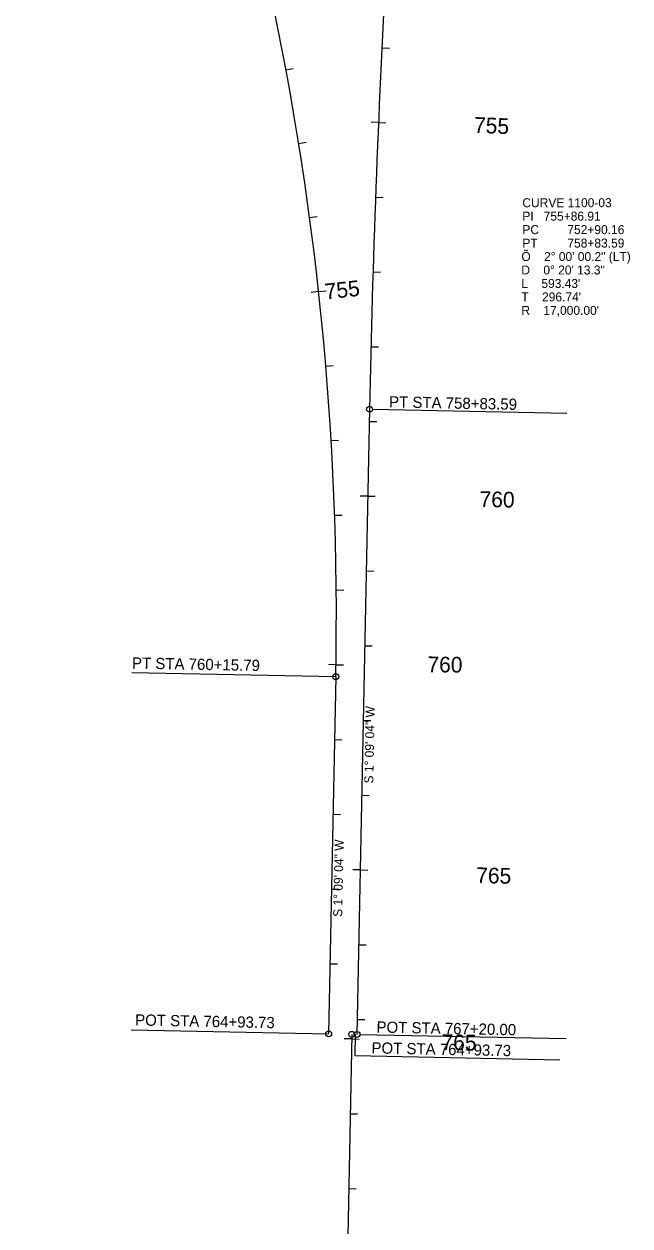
# Model space of a CAD drawing. Extents: x 2819977 to 2827606, y 113942 to 150283.
# Drawn here: x 2823322 to 2824133, y 142125 to 143732 of the extents above; entities that cross this region are included whole.
import ezdxf

# ---------------------------------------------------------------- set-up
doc = ezdxf.new("R2010")
doc.units = 0
for name, color, linetype in [('Level 63', 7, 'Continuous'), ('Roadway-Safety', 7, 'Continuous'), ('Roadway-Signs', 7, 'Continuous'), ('Roadway-Walls', 7, 'Continuous'), ('Utility-Power', 7, 'Continuous')]:
    doc.layers.add(name, color=color, linetype=linetype)

msp = doc.modelspace()

# ---------------------------------------------------------------- linework, layer by layer
at = {"layer": 'Level 63'}
for centre in [(2823784.6, 143217), (2823760.8, 142380.9), (2823767.8, 142380.8)]:
    msp.add_circle(centre, 4, dxfattribs=at)
at = {"layer": 'Roadway-Safety'}
for p, q in [((2823788.6, 143217), (2824048.3, 143211.7)), ((2823466.6, 142864.9), (2823739.4, 142859.4)), ((2823465.6, 142386.9), (2823729.8, 142381.6)), ((2823764.8, 142380.9), (2823765.5, 142380.8)), ((2823765.5, 142380.8), (2823765, 142352.5)), ((2823771.8, 142380.7), (2824047.7, 142375.2)), ((2823765, 142352.5), (2824039.1, 142347))]:
    msp.add_line(p, q, dxfattribs=at)
at = {"layer": 'Utility-Power'}
for p, q in [((2823801.2, 143700.3), (2823811.2, 143699.8)), ((2823672.8, 143671.1), (2823682.6, 143672.9)), ((2823796.6, 143600.4), (2823786.6, 143600.9)), ((2823796.6, 143600.4), (2823806.6, 143600)), ((2823689.8, 143572.5), (2823699.7, 143574.1)), ((2823792.6, 143500.5), (2823802.6, 143500.1)), ((2823704.4, 143473.6), (2823714.3, 143474.9)), ((2823789.3, 143400.6), (2823799.2, 143400.3)), ((2823716.5, 143374.3), (2823706.6, 143373.3)), ((2823716.5, 143374.3), (2823726.5, 143375.4)), ((2823786.5, 143300.6), (2823796.5, 143300.4)), ((2823726.1, 143274.8), (2823736.1, 143275.6)), ((2823784.6, 143217), (2823767.8, 142380.8)), ((2823784.2, 143200.6), (2823794.2, 143200.4)), ((2823733.3, 143175.1), (2823743.2, 143175.7)), ((2823782.2, 143100.7), (2823772.2, 143100.9)), ((2823782.2, 143100.7), (2823792.2, 143100.5)), ((2823737.9, 143075.2), (2823747.9, 143075.5)), ((2823780.2, 143000.7), (2823790.2, 143000.5)), ((2823740, 142975.2), (2823750, 142975.3)), ((2823778.2, 142900.7), (2823788.2, 142900.5)), ((2823739.7, 142875.2), (2823729.7, 142875.4)), ((2823739.7, 142875.2), (2823749.7, 142875)), ((2823739.4, 142859.4), (2823729.8, 142381.6)), ((2823776.2, 142800.7), (2823786.2, 142800.5)), ((2823737.7, 142775.2), (2823747.7, 142775)), ((2823774.2, 142700.7), (2823784.2, 142700.5)), ((2823735.7, 142675.2), (2823745.7, 142675)), ((2823772.2, 142600.8), (2823762.2, 142601)), ((2823772.2, 142600.8), (2823782.2, 142600.6)), ((2823733.7, 142575.3), (2823743.7, 142575.1)), ((2823770.2, 142500.8), (2823780.2, 142500.6)), ((2823731.7, 142475.3), (2823741.7, 142475.1)), ((2823768.2, 142400.8), (2823778.2, 142400.6)), ((2823760.8, 142380.9), (2823701.1, 139408.5)), ((2823760.6, 142374.7), (2823750.6, 142374.9)), ((2823760.6, 142374.7), (2823770.6, 142374.5)), ((2823758.6, 142274.7), (2823768.6, 142274.5)), ((2823756.6, 142174.7), (2823766.6, 142174.5))]:
    msp.add_line(p, q, dxfattribs=at)
for centre in [(2823739.4, 142859.4), (2823729.8, 142381.6)]:
    msp.add_circle(centre, 4, dxfattribs=at)
for centre, radius, start, end in [((2819740.2, 142939.8), 4000, 358.849, 26.4209), ((2840781.1, 142875.6), 17000, 176.84893, 178.84897)]:
    msp.add_arc(centre, radius, start, end, dxfattribs=at)

# ---------------------------------------------------------------- texts
at = {"layer": 'Roadway-Safety'}
for s, p in [('PT STA 758+83.59', (2823810.6, 143219.5)), ('PT STA 760+15.79', (2823466.7, 142870.2)), ('POT STA 764+93.73', (2823470.9, 142392.8)), ('POT STA 767+20.00', (2823793.8, 142383.3)), ('POT STA 764+93.73', (2823787.1, 142355.4))]:
    msp.add_text(s, height=15, rotation=358.849, dxfattribs=at).set_placement(p)
at = {"layer": 'Roadway-Signs'}
for p in [(2823789.5, 142716.3), (2823747.9, 142537.9)]:
    msp.add_text('S 1%%d 09\' 04" W', height=12, rotation=88.849, dxfattribs=at).set_placement(p)
at = {"layer": 'Roadway-Walls'}
for s, p in [('CURVE 1100-03', (2823989, 143487.2)), ('PI   755+86.91', (2823989, 143469.2)), ('PC', (2823989, 143451.2)), ('752+90.16', (2824049.2, 143451.2)), ('PT', (2823989, 143433.2)), ('758+83.59', (2824049.2, 143433.2)), ('Õ    2%%d 00\' 00.2" (LT)', (2823987.7, 143415.2)), ('D    0%%d 20\' 13.3"', (2823987.7, 143397.2)), ("L    593.43'", (2823987.7, 143379.2)), ("T    296.74'", (2823987.7, 143361.2)), ("R    17,000.00'", (2823987.7, 143343.2))]:
    msp.add_text(s, height=12, dxfattribs=at).set_placement(p)
at = {"layer": 'Utility-Power'}
for s, rotation, p in [(' 755', 357.5561, (2823916.2, 143587.2)), (' 755', 6.2372, (2823718.1, 143362.9)), (' 760', 358.849, (2823923.8, 143086.5)), (' 760', 359.0752, (2823854.1, 142865.5)), (' 765', 358.849, (2823919.3, 142583.4)), (' 765', 358.849, (2823872.9, 142360.3))]:
    msp.add_text(s, height=21, rotation=rotation, dxfattribs=at).set_placement(p)

doc.saveas('drawing.dxf')
